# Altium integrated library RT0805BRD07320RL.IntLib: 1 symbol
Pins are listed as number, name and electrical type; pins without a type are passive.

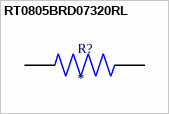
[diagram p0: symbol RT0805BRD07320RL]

## RT0805BRD07320RL
designator R?
RES SMD 320 OHM 0.1% 1/8W 0805; MP: RT0805BRD07320RL
footprint RESC2012X60N
pins: 1, 2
